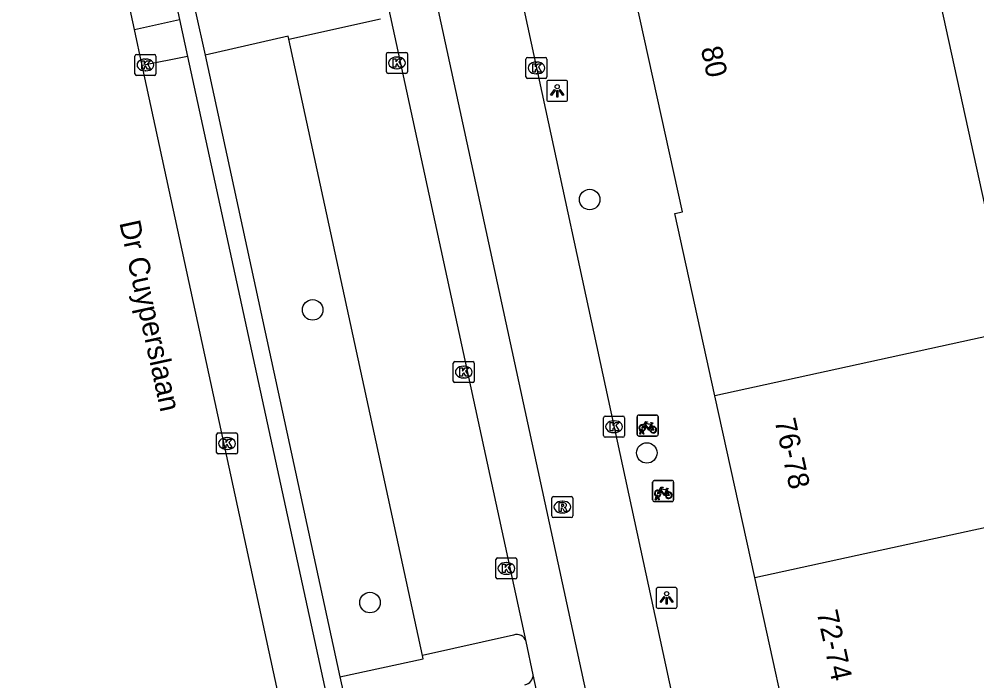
# Model space of a CAD drawing. Extents: x 160557 to 161245, y 385330 to 386505.
# Drawn here: x 160734.82 to 160780.49, y 385796.82 to 385828.37 of the extents above; entities that cross this region are included whole.
import ezdxf

# ---------------------------------------------------------------- set-up
doc = ezdxf.new("R2010")
doc.units = 0
for name, color, linetype in [('IMGEO_Boom', 7, 'Continuous'), ('IMGEO_Fietsenrek', 7, 'Continuous'), ('IMGEO_Fietspad_gesloten', 7, 'Continuous'), ('IMGEO_Kolk', 7, 'Continuous'), ('IMGEO_Lichtpunt', 7, 'Continuous'), ('IMGEO_Openbare_ruimte_label', 7, 'Continuous'), ('IMGEO_Pand', 7, 'Continuous'), ('IMGEO_Pand_nummerreeks', 7, 'Continuous'), ('IMGEO_Parkeervlak_open', 7, 'Continuous'), ('IMGEO_Rijbaan_lokaal_gesloten', 7, 'Continuous'), ('IMGEO_Rioolput', 7, 'Continuous'), ('IMGEO_Voetpad_open', 7, 'Continuous')]:
    doc.layers.add(name, color=color, linetype=linetype)

msp = doc.modelspace()

# ---------------------------------------------------------------- linework, layer by layer
at = {"layer": 'IMGEO_Boom'}
for centre in [(160762.023, 385819.771), (160748.812, 385814.509), (160764.746, 385807.689), (160751.546, 385800.554)]:
    msp.add_circle(centre, 0.489, dxfattribs=at)
at = {"layer": 'IMGEO_Fietsenrek'}
for p, q in [((160764.362, 385809.495), (160765.203, 385809.495)), ((160765.203, 385809.495), (160764.362, 385809.495)), ((160764.287, 385808.57), (160764.287, 385809.411)), ((160764.287, 385809.411), (160764.287, 385808.57)), ((160764.974, 385809.044), (160765.01, 385808.949)), ((160765.287, 385809.42), (160765.287, 385808.579)), ((160765.287, 385808.579), (160765.287, 385809.42)), ((160764.414, 385808.579), (160764.453, 385808.739)), ((160764.448, 385808.579), (160764.414, 385808.579)), ((160764.483, 385808.727), (160764.448, 385808.579)), ((160764.525, 385808.751), (160764.524, 385808.755)), ((160764.566, 385808.579), (160764.532, 385808.721)), ((160764.556, 385808.762), (160764.557, 385808.755)), ((160764.564, 385808.725), (160764.599, 385808.579)), ((160764.599, 385808.579), (160764.566, 385808.579)), ((160765.212, 385808.495), (160764.371, 385808.495)), ((160764.371, 385808.495), (160765.212, 385808.495)), ((160765.101, 385806.373), (160765.942, 385806.373)), ((160765.942, 385806.373), (160765.101, 385806.373)), ((160766.026, 385806.298), (160766.026, 385805.457)), ((160766.026, 385805.457), (160766.026, 385806.298)), ((160765.026, 385805.448), (160765.026, 385806.289)), ((160765.026, 385806.289), (160765.026, 385805.448)), ((160765.713, 385805.922), (160765.749, 385805.827)), ((160765.153, 385805.457), (160765.192, 385805.617)), ((160765.187, 385805.457), (160765.153, 385805.457)), ((160765.222, 385805.605), (160765.187, 385805.457)), ((160765.264, 385805.629), (160765.263, 385805.633)), ((160765.305, 385805.457), (160765.271, 385805.599)), ((160765.295, 385805.64), (160765.296, 385805.633)), ((160765.303, 385805.603), (160765.338, 385805.457)), ((160765.338, 385805.457), (160765.305, 385805.457)), ((160765.951, 385805.373), (160765.11, 385805.373)), ((160765.11, 385805.373), (160765.951, 385805.373))]:
    msp.add_line(p, q, dxfattribs=at)
for points in [[(160764.6, 385809.021), (160764.695, 385809.185), (160764.781, 385809.171), (160764.783, 385809.162), (160764.727, 385809.151), (160764.7, 385809.106), (160764.956, 385809.065)], [(160764.943, 385809.04), (160764.686, 385809.081), (160764.669, 385809.052), (160764.836, 385808.832), (160764.943, 385809.04)], [(160764.956, 385809.065), (160764.981, 385809.114), (160764.975, 385809.118), (160764.952, 385809.122), (160764.94, 385809.129), (160764.939, 385809.132), (160764.941, 385809.137), (160765.036, 385809.122), (160765.038, 385809.112), (160765.028, 385809.099), (160765.016, 385809.093), (160765.002, 385809.099), (160764.974, 385809.044)], [(160764.621, 385808.969), (160764.569, 385808.879), (160764.529, 385808.854), (160764.53, 385808.901), (160764.585, 385808.995)], [(160764.896, 385808.777), (160764.846, 385808.777), (160764.655, 385809.028), (160764.636, 385808.996)], [(160764.991, 385808.942), (160764.961, 385809.019), (160764.852, 385808.801), (160764.895, 385808.801)], [(160764.925, 385808.801), (160765.045, 385808.8), (160765.001, 385808.914)], [(160765.021, 385808.921), (160765.076, 385808.776), (160764.926, 385808.776)], [(160765.36, 385805.847), (160765.308, 385805.757), (160765.268, 385805.732), (160765.269, 385805.779), (160765.324, 385805.873)], [(160765.339, 385805.899), (160765.434, 385806.063), (160765.52, 385806.049), (160765.522, 385806.04), (160765.466, 385806.029), (160765.439, 385805.984), (160765.695, 385805.943)], [(160765.635, 385805.655), (160765.585, 385805.655), (160765.394, 385805.906), (160765.375, 385805.874)], [(160765.682, 385805.918), (160765.425, 385805.959), (160765.408, 385805.93), (160765.575, 385805.71), (160765.682, 385805.918)], [(160765.73, 385805.82), (160765.7, 385805.897), (160765.591, 385805.679), (160765.634, 385805.679)], [(160765.695, 385805.943), (160765.72, 385805.992), (160765.714, 385805.996), (160765.691, 385806), (160765.679, 385806.007), (160765.678, 385806.01), (160765.68, 385806.015), (160765.775, 385806), (160765.777, 385805.99), (160765.767, 385805.977), (160765.755, 385805.971), (160765.741, 385805.977), (160765.713, 385805.922)], [(160765.664, 385805.679), (160765.784, 385805.678), (160765.74, 385805.792)], [(160765.76, 385805.799), (160765.815, 385805.654), (160765.665, 385805.654)]]:
    msp.add_lwpolyline(points, dxfattribs=at)
for centre, radius, start, end in [((160764.365, 385809.417), 0.0779, 92.4484, 184.2845), ((160764.365, 385809.417), 0.0779, 92.4484, 184.2845), ((160765.209, 385809.417), 0.0779, 2.4484, 94.2845), ((160765.209, 385809.417), 0.0779, 2.4484, 94.2845), ((160764.527, 385808.88), 0.159, 62.6766, 242.1369), ((160764.527, 385808.88), 0.129, 63.3192, 238.903), ((160764.507, 385808.751), 0.0499, 12.8025, 158.6934), ((160764.527, 385808.88), 0.159, 253.9967, 271.7867), ((160764.507, 385808.751), 0.0174, 12.8025, 163.4502), ((160764.527, 385808.88), 0.129, 253.415, 269.0204), ((160764.527, 385808.88), 0.129, 283.6043, 43.4302), ((160764.527, 385808.88), 0.159, 283.5766, 46.6042), ((160765.054, 385808.796), 0.159, 113.3408, 178.3217), ((160765.054, 385808.796), 0.159, 187.0065, 105.7708), ((160765.054, 385808.796), 0.129, 113.923, 177.9556), ((160765.054, 385808.796), 0.129, 188.6715, 104.5883), ((160765.209, 385808.573), 0.0779, 272.4484, 4.2845), ((160765.209, 385808.573), 0.0779, 272.4484, 4.2845), ((160764.365, 385808.573), 0.0779, 182.4484, 274.2845), ((160764.365, 385808.573), 0.0779, 182.4484, 274.2845), ((160765.104, 385806.295), 0.0779, 92.4484, 184.2845), ((160765.104, 385806.295), 0.0779, 92.4484, 184.2845), ((160765.948, 385806.295), 0.0779, 2.4484, 94.2845), ((160765.948, 385806.295), 0.0779, 2.4484, 94.2845), ((160765.266, 385805.758), 0.159, 62.6766, 242.1369), ((160765.266, 385805.758), 0.129, 63.3192, 238.903), ((160765.266, 385805.758), 0.129, 283.6043, 43.4302), ((160765.266, 385805.758), 0.159, 283.5766, 46.6042), ((160765.104, 385805.451), 0.0779, 182.4484, 274.2845), ((160765.104, 385805.451), 0.0779, 182.4484, 274.2845), ((160765.246, 385805.629), 0.0499, 12.8025, 158.6934), ((160765.266, 385805.758), 0.159, 253.9967, 271.7867), ((160765.246, 385805.629), 0.0174, 12.8025, 163.4502), ((160765.266, 385805.758), 0.129, 253.415, 269.0204), ((160765.793, 385805.674), 0.159, 113.3408, 178.3217), ((160765.793, 385805.674), 0.159, 187.0065, 105.7708), ((160765.793, 385805.674), 0.129, 113.923, 177.9556), ((160765.793, 385805.674), 0.129, 188.6715, 104.5883), ((160765.948, 385805.451), 0.0779, 272.4484, 4.2845), ((160765.948, 385805.451), 0.0779, 272.4484, 4.2845)]:
    msp.add_arc(centre, radius, start, end, dxfattribs=at)
at = {"layer": 'IMGEO_Fietspad_gesloten'}
for points in [[(160775.118, 385735.103), (160749.654, 385852.647), (160746.978, 385864.559), (160746.687, 385864.512)], [(160753.194, 385855.146), (160753.582, 385853.359), (160768.677, 385783.529), (160779.078, 385735.819)]]:
    msp.add_lwpolyline(points, dxfattribs=at)
at = {"layer": 'IMGEO_Kolk'}
for p, q in [((160740.338, 385825.762), (160740.338, 385826.614)), ((160740.413, 385826.688), (160741.265, 385826.688)), ((160740.826, 385826.468), (160740.851, 385826.468)), ((160741.339, 385826.614), (160741.339, 385825.762)), ((160752.333, 385825.861), (160752.333, 385826.713)), ((160752.408, 385826.787), (160753.26, 385826.787)), ((160752.821, 385826.567), (160752.846, 385826.567)), ((160753.334, 385826.713), (160753.334, 385825.861)), ((160758.985, 385825.619), (160758.985, 385826.471)), ((160759.06, 385826.545), (160759.912, 385826.545)), ((160759.986, 385826.471), (160759.986, 385825.619)), ((160752.844, 385826.007), (160752.819, 385826.007)), ((160759.473, 385826.325), (160759.498, 385826.325)), ((160741.265, 385825.688), (160740.413, 385825.688)), ((160740.849, 385825.908), (160740.824, 385825.908)), ((160753.26, 385825.787), (160752.408, 385825.787)), ((160759.912, 385825.545), (160759.06, 385825.545)), ((160759.496, 385825.765), (160759.471, 385825.765)), ((160755.516, 385811.118), (160755.516, 385811.97)), ((160755.591, 385812.044), (160756.443, 385812.044)), ((160756.004, 385811.824), (160756.029, 385811.824)), ((160756.517, 385811.97), (160756.517, 385811.118)), ((160756.443, 385811.044), (160755.591, 385811.044)), ((160756.027, 385811.264), (160756.002, 385811.264)), ((160762.683, 385808.514), (160762.683, 385809.366)), ((160762.758, 385809.44), (160763.61, 385809.44)), ((160763.171, 385809.22), (160763.196, 385809.22)), ((160763.684, 385809.366), (160763.684, 385808.514)), ((160744.304, 385808.639), (160745.156, 385808.639)), ((160763.194, 385808.66), (160763.169, 385808.66)), ((160744.229, 385807.713), (160744.229, 385808.565)), ((160744.717, 385808.419), (160744.742, 385808.419)), ((160745.23, 385808.565), (160745.23, 385807.713)), ((160763.61, 385808.44), (160762.758, 385808.44)), ((160744.74, 385807.859), (160744.715, 385807.859)), ((160745.156, 385807.639), (160744.304, 385807.639)), ((160757.625, 385802.683), (160758.477, 385802.683)), ((160757.55, 385801.757), (160757.55, 385802.609)), ((160758.038, 385802.463), (160758.063, 385802.463)), ((160758.551, 385802.609), (160758.551, 385801.757)), ((160758.061, 385801.903), (160758.036, 385801.903)), ((160758.477, 385801.683), (160757.625, 385801.683))]:
    msp.add_line(p, q, dxfattribs=at)
for points in [[(160740.338, 385825.762), (160740.338, 385826.614)], [(160740.413, 385826.688), (160741.265, 385826.688)], [(160740.659, 385826.388), (160740.782, 385826.388), (160740.782, 385826.237), (160740.912, 385826.388), (160741.076, 385826.388), (160740.93, 385826.237), (160741.083, 385825.988), (160740.931, 385825.988), (160740.846, 385826.152), (160740.782, 385826.085), (160740.782, 385825.988), (160740.659, 385825.988), (160740.659, 385826.388)], [(160741.339, 385826.614), (160741.339, 385825.762)], [(160752.333, 385825.861), (160752.333, 385826.713)], [(160752.408, 385826.787), (160753.26, 385826.787)], [(160752.654, 385826.487), (160752.777, 385826.487), (160752.777, 385826.336), (160752.907, 385826.487), (160753.071, 385826.487), (160752.925, 385826.336), (160753.078, 385826.087), (160752.926, 385826.087), (160752.841, 385826.251), (160752.777, 385826.184), (160752.777, 385826.087), (160752.654, 385826.087), (160752.654, 385826.487)], [(160753.334, 385826.713), (160753.334, 385825.861)], [(160758.985, 385825.619), (160758.985, 385826.471)], [(160759.06, 385826.545), (160759.912, 385826.545)], [(160759.986, 385826.471), (160759.986, 385825.619)], [(160759.306, 385826.245), (160759.429, 385826.245), (160759.429, 385826.094), (160759.559, 385826.245), (160759.723, 385826.245), (160759.577, 385826.094), (160759.73, 385825.845), (160759.578, 385825.845), (160759.493, 385826.009), (160759.429, 385825.942), (160759.429, 385825.845), (160759.306, 385825.845), (160759.306, 385826.245)], [(160741.265, 385825.688), (160740.413, 385825.688)], [(160753.26, 385825.787), (160752.408, 385825.787)], [(160759.912, 385825.545), (160759.06, 385825.545)], [(160755.516, 385811.118), (160755.516, 385811.97)], [(160755.591, 385812.044), (160756.443, 385812.044)], [(160756.517, 385811.97), (160756.517, 385811.118)], [(160755.837, 385811.744), (160755.96, 385811.744), (160755.96, 385811.593), (160756.09, 385811.744), (160756.254, 385811.744), (160756.108, 385811.593), (160756.261, 385811.344), (160756.109, 385811.344), (160756.024, 385811.508), (160755.96, 385811.441), (160755.96, 385811.344), (160755.837, 385811.344), (160755.837, 385811.744)], [(160756.443, 385811.044), (160755.591, 385811.044)], [(160762.683, 385808.514), (160762.683, 385809.366)], [(160762.758, 385809.44), (160763.61, 385809.44)], [(160763.004, 385809.14), (160763.127, 385809.14), (160763.127, 385808.989), (160763.257, 385809.14), (160763.421, 385809.14), (160763.275, 385808.989), (160763.428, 385808.74), (160763.276, 385808.74), (160763.191, 385808.904), (160763.127, 385808.837), (160763.127, 385808.74), (160763.004, 385808.74), (160763.004, 385809.14)], [(160763.684, 385809.366), (160763.684, 385808.514)], [(160744.304, 385808.639), (160745.156, 385808.639)], [(160744.229, 385807.713), (160744.229, 385808.565)], [(160744.55, 385808.339), (160744.673, 385808.339), (160744.673, 385808.188), (160744.803, 385808.339), (160744.967, 385808.339), (160744.821, 385808.188), (160744.974, 385807.939), (160744.822, 385807.939), (160744.737, 385808.103), (160744.673, 385808.036), (160744.673, 385807.939), (160744.55, 385807.939), (160744.55, 385808.339)], [(160745.23, 385808.565), (160745.23, 385807.713)], [(160763.61, 385808.44), (160762.758, 385808.44)], [(160745.156, 385807.639), (160744.304, 385807.639)], [(160757.625, 385802.683), (160758.477, 385802.683)], [(160757.55, 385801.757), (160757.55, 385802.609)], [(160757.871, 385802.383), (160757.994, 385802.383), (160757.994, 385802.232), (160758.124, 385802.383), (160758.288, 385802.383), (160758.142, 385802.232), (160758.295, 385801.983), (160758.143, 385801.983), (160758.058, 385802.147), (160757.994, 385802.08), (160757.994, 385801.983), (160757.871, 385801.983), (160757.871, 385802.383)], [(160758.551, 385802.609), (160758.551, 385801.757)], [(160758.477, 385801.683), (160757.625, 385801.683)]]:
    msp.add_lwpolyline(points, dxfattribs=at)
for centre, start, end in [((160740.415, 385826.612), 91.552, 178.448), ((160740.415, 385826.612), 91.552, 178.448), ((160741.263, 385826.612), 1.552, 88.448), ((160741.263, 385826.612), 1.552, 88.448), ((160752.41, 385826.711), 91.552, 178.448), ((160752.41, 385826.711), 91.552, 178.448), ((160753.258, 385826.711), 1.552, 88.448), ((160753.258, 385826.711), 1.552, 88.448), ((160759.062, 385826.469), 91.552, 178.448), ((160759.062, 385826.469), 91.552, 178.448), ((160759.91, 385826.469), 1.552, 88.448), ((160759.91, 385826.469), 1.552, 88.448), ((160740.415, 385825.764), 181.552, 268.448), ((160740.415, 385825.764), 181.552, 268.448), ((160741.263, 385825.764), 271.552, 358.448), ((160741.263, 385825.764), 271.552, 358.448), ((160752.41, 385825.863), 181.552, 268.448), ((160752.41, 385825.863), 181.552, 268.448), ((160753.258, 385825.863), 271.552, 358.448), ((160753.258, 385825.863), 271.552, 358.448), ((160759.062, 385825.621), 181.552, 268.448), ((160759.062, 385825.621), 181.552, 268.448), ((160759.91, 385825.621), 271.552, 358.448), ((160759.91, 385825.621), 271.552, 358.448), ((160755.593, 385811.968), 91.552, 178.448), ((160755.593, 385811.968), 91.552, 178.448), ((160756.441, 385811.968), 1.552, 88.448), ((160756.441, 385811.968), 1.552, 88.448), ((160755.593, 385811.12), 181.552, 268.448), ((160755.593, 385811.12), 181.552, 268.448), ((160756.441, 385811.12), 271.552, 358.448), ((160756.441, 385811.12), 271.552, 358.448), ((160762.76, 385809.364), 91.552, 178.448), ((160762.76, 385809.364), 91.552, 178.448), ((160763.608, 385809.364), 1.552, 88.448), ((160763.608, 385809.364), 1.552, 88.448), ((160744.306, 385808.563), 91.552, 178.448), ((160744.306, 385808.563), 91.552, 178.448), ((160745.154, 385808.563), 1.552, 88.448), ((160745.154, 385808.563), 1.552, 88.448), ((160762.76, 385808.516), 181.552, 268.448), ((160762.76, 385808.516), 181.552, 268.448), ((160763.608, 385808.516), 271.552, 358.448), ((160763.608, 385808.516), 271.552, 358.448), ((160744.306, 385807.715), 181.552, 268.448), ((160744.306, 385807.715), 181.552, 268.448), ((160745.154, 385807.715), 271.552, 358.448), ((160745.154, 385807.715), 271.552, 358.448), ((160757.627, 385802.607), 91.552, 178.448), ((160757.627, 385802.607), 91.552, 178.448), ((160758.475, 385802.607), 1.552, 88.448), ((160758.475, 385802.607), 1.552, 88.448), ((160757.627, 385801.759), 181.552, 268.448), ((160757.627, 385801.759), 181.552, 268.448), ((160758.475, 385801.759), 271.552, 358.448), ((160758.475, 385801.759), 271.552, 358.448)]:
    msp.add_arc(centre, 0.0765, start, end, dxfattribs=at)
for centre, major_axis, ratio, start_param, end_param in [((160740.825, 385826.188), (-0.387, 0.002), 0.722429, 4.712389, 7.853982), ((160740.85, 385826.188), (-0.39, 0.002), 0.717154, 1.570796, 4.712389), ((160752.82, 385826.287), (-0.387, 0.002), 0.722429, 4.712389, 7.853982), ((160752.845, 385826.287), (-0.39, 0.002), 0.717154, 1.570796, 4.712389), ((160759.472, 385826.045), (-0.387, 0.002), 0.722429, 4.712389, 7.853982), ((160759.497, 385826.045), (-0.39, 0.002), 0.717154, 1.570796, 4.712389), ((160756.003, 385811.544), (-0.387, 0.002), 0.722429, 4.712389, 7.853982), ((160756.028, 385811.544), (-0.39, 0.002), 0.717154, 1.570796, 4.712389), ((160763.17, 385808.94), (-0.387, 0.002), 0.722429, 4.712389, 7.853982), ((160763.195, 385808.94), (-0.39, 0.002), 0.717154, 1.570796, 4.712389), ((160744.716, 385808.139), (-0.387, 0.002), 0.722429, 4.712389, 7.853982), ((160744.741, 385808.139), (-0.39, 0.002), 0.717154, 1.570796, 4.712389), ((160758.037, 385802.183), (-0.387, 0.002), 0.722429, 4.712389, 7.853982), ((160758.062, 385802.183), (-0.39, 0.002), 0.717154, 1.570796, 4.712389)]:
    msp.add_ellipse(centre, major_axis=major_axis, ratio=ratio, start_param=start_param, end_param=end_param, dxfattribs=at)
at = {"layer": 'IMGEO_Lichtpunt'}
for p, q in [((160759.975, 385825.357), (160759.975, 385824.55)), ((160759.975, 385825.357), (160759.975, 385824.55)), ((160760.877, 385825.452), (160760.069, 385825.452)), ((160760.877, 385825.452), (160760.069, 385825.452)), ((160760.971, 385824.55), (160760.971, 385825.357)), ((160760.971, 385824.55), (160760.971, 385825.357)), ((160760.069, 385824.456), (160760.877, 385824.456)), ((160760.069, 385824.456), (160760.877, 385824.456)), ((160766.095, 385801.275), (160765.287, 385801.275)), ((160766.095, 385801.275), (160765.287, 385801.275)), ((160765.193, 385801.18), (160765.193, 385800.373)), ((160765.193, 385801.18), (160765.193, 385800.373)), ((160766.189, 385800.373), (160766.189, 385801.18)), ((160766.189, 385800.373), (160766.189, 385801.18)), ((160765.287, 385800.279), (160766.095, 385800.279)), ((160765.287, 385800.279), (160766.095, 385800.279))]:
    msp.add_line(p, q, dxfattribs=at)
for points in [[(160760.349, 385825.021), (160760.388, 385824.993), (160760.2, 385824.731), (160760.162, 385824.758), (160760.349, 385825.021)], [(160760.561, 385824.993), (160760.599, 385825.02), (160760.786, 385824.758), (160760.747, 385824.73), (160760.561, 385824.993)], [(160760.451, 385824.973), (160760.498, 385824.973), (160760.498, 385824.651), (160760.451, 385824.651), (160760.451, 385824.973)], [(160765.567, 385800.844), (160765.606, 385800.816), (160765.418, 385800.554), (160765.38, 385800.581), (160765.567, 385800.844)], [(160765.779, 385800.816), (160765.817, 385800.843), (160766.004, 385800.581), (160765.965, 385800.553), (160765.779, 385800.816)], [(160765.669, 385800.796), (160765.716, 385800.796), (160765.716, 385800.474), (160765.669, 385800.474), (160765.669, 385800.796)]]:
    msp.add_lwpolyline(points, dxfattribs=at)
for centre in [(160760.474, 385825.155), (160765.692, 385800.978)]:
    msp.add_circle(centre, 0.0994, dxfattribs=at)
for centre, start, end in [((160760.069, 385825.357), 90, 180), ((160760.069, 385825.357), 90, 180), ((160760.877, 385825.357), 0, 90), ((160760.877, 385825.357), 0, 90), ((160760.069, 385824.55), 180, 270), ((160760.069, 385824.55), 180, 270), ((160760.877, 385824.55), 270, 0), ((160760.877, 385824.55), 270, 360), ((160765.287, 385801.18), 90, 180), ((160765.287, 385801.18), 90, 180), ((160766.095, 385801.18), 0, 90), ((160766.095, 385801.18), 0, 90), ((160765.287, 385800.373), 180, 270), ((160765.287, 385800.373), 180, 270), ((160766.095, 385800.373), 270, 0), ((160766.095, 385800.373), 270, 360)]:
    msp.add_arc(centre, 0.0946, start, end, dxfattribs=at)
at = {"layer": 'IMGEO_Pand'}
for points in [[(160797.582, 385839.533), (160777.43, 385835.122), (160782.162, 385813.51)], [(160767.998, 385810.411), (160766.088, 385819.108), (160766.446, 385819.186), (160763.205, 385833.915)], [(160782.162, 385813.51), (160767.998, 385810.411)], [(160769.9, 385801.747), (160767.998, 385810.411)], [(160769.9, 385801.747), (160774.775, 385802.815), (160793.37, 385806.85), (160798.295, 385807.928)], [(160772.013, 385792.125), (160769.9, 385801.747)]]:
    msp.add_lwpolyline(points, dxfattribs=at)
at = {"layer": 'IMGEO_Parkeervlak_open'}
msp.add_lwpolyline([(160754.05, 385798.028), (160747.68, 385827.413)], dxfattribs=at)
at = {"layer": 'IMGEO_Rijbaan_lokaal_gesloten'}
for points in [[(160740.309, 385827.873), (160734.816, 385853.141)], [(160740.682, 385826.157), (160740.309, 385827.873)], [(160755.198, 385759.167), (160740.682, 385826.157)]]:
    msp.add_lwpolyline(points, dxfattribs=at)
at = {"layer": 'IMGEO_Rioolput'}
for p, q in [((160760.218, 385804.683), (160760.218, 385805.535)), ((160760.293, 385805.609), (160761.145, 385805.609)), ((160760.706, 385805.389), (160760.731, 385805.389)), ((160761.219, 385805.535), (160761.219, 385804.683)), ((160761.145, 385804.609), (160760.293, 385804.609)), ((160760.729, 385804.829), (160760.704, 385804.829))]:
    msp.add_line(p, q, dxfattribs=at)
for points in [[(160760.218, 385804.683), (160760.218, 385805.535)], [(160760.293, 385805.609), (160761.145, 385805.609)], [(160761.219, 385805.535), (160761.219, 385804.683)], [(160760.807, 385805.307), (160760.555, 385805.309), (160760.555, 385804.909)], [(160760.555, 385804.909), (160760.679, 385804.909), (160760.679, 385805.071), (160760.69, 385805.071)], [(160760.733, 385805.228), (160760.679, 385805.228), (160760.679, 385805.147)], [(160760.679, 385805.147), (160760.731, 385805.147)], [(160760.737, 385805.042), (160760.808, 385804.909), (160760.948, 385804.909), (160760.883, 385805.035)], [(160761.145, 385804.609), (160760.293, 385804.609)]]:
    msp.add_lwpolyline(points, dxfattribs=at)
for centre, radius, start, end in [((160760.295, 385805.533), 0.0765, 91.552, 178.448), ((160760.295, 385805.533), 0.0765, 91.552, 178.448), ((160761.143, 385805.533), 0.0765, 1.552, 88.448), ((160761.143, 385805.533), 0.0765, 1.552, 88.448), ((160760.689, 385805.018), 0.0533, 26.0293, 88.6989), ((160760.715, 385805.336), 0.19, 274.7715, 282.9687), ((160760.739, 385805.132), 0.0964, 77.0061, 93.1865), ((160760.753, 385805.189), 0.0378, 276.6634, 79.6772), ((160760.806, 385805.197), 0.109, 350.3612, 89.416), ((160760.804, 385805.197), 0.112, 277.5842, 350.9817), ((160760.788, 385804.982), 0.108, 29.5134, 73.7905), ((160760.295, 385804.685), 0.0765, 181.552, 268.448), ((160760.295, 385804.685), 0.0765, 181.552, 268.448), ((160761.143, 385804.685), 0.0765, 271.552, 358.448), ((160761.143, 385804.685), 0.0765, 271.552, 358.448)]:
    msp.add_arc(centre, radius, start, end, dxfattribs=at)
for centre, major_axis, ratio, start_param, end_param in [((160760.705, 385805.109), (-0.387, 0.002), 0.722429, 4.712389, 7.853982), ((160760.73, 385805.109), (-0.39, 0.002), 0.717154, 1.570796, 4.712389)]:
    msp.add_ellipse(centre, major_axis=major_axis, ratio=ratio, start_param=start_param, end_param=end_param, dxfattribs=at)
at = {"layer": 'IMGEO_Voetpad_open'}
for points in [[(160737.667, 385850.35), (160742.46, 385828.352)], [(160743.233, 385828.714), (160743.679, 385826.657)], [(160758.99, 385798.701), (160752.445, 385828.891)], [(160740.309, 385827.873), (160742.46, 385828.352)], [(160742.46, 385828.352), (160742.843, 385826.594)], [(160747.68, 385827.413), (160752.051, 385828.391)], [(160747.68, 385827.413), (160747.646, 385827.566), (160743.679, 385826.657)], [(160742.843, 385826.594), (160740.682, 385826.157)], [(160742.843, 385826.594), (160756.782, 385762.497)], [(160743.679, 385826.657), (160750.11, 385797.017)], [(160758.385, 385799.005), (160754.05, 385798.028)], [(160759.334, 385797.113), (160758.99, 385798.701)], [(160750.11, 385797.017), (160754.084, 385797.87), (160754.05, 385798.028)], [(160750.11, 385797.017), (160750.573, 385794.958)], [(160767.479, 385759.49), (160759.334, 385797.113)]]:
    msp.add_lwpolyline(points, dxfattribs=at)
for centre, radius, start, end in [((160758.533, 385798.546), 0.482, 18.7172, 107.9256), ((160758.838, 385797.119), 0.496, 281.4295, 359.3589)]:
    msp.add_arc(centre, radius, start, end, dxfattribs=at)

# ---------------------------------------------------------------- texts
at = {"layer": 'IMGEO_Openbare_ruimte_label'}
msp.add_text('Dr Cuyperslaan', height=1, rotation=282.2989, dxfattribs=at).set_placement((160739.588, 385818.67))
at = {"layer": 'IMGEO_Pand_nummerreeks'}
for s, rotation, p in [('80', 282.4101, (160767.314, 385826.972)), ('76-78', 282.3839, (160770.837, 385809.231)), ('72-74', 282.3839, (160772.844, 385800.091))]:
    msp.add_text(s, height=1, rotation=rotation, dxfattribs=at).set_placement(p)

doc.saveas('drawing.dxf')
